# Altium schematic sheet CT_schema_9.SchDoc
size 391 x 238 mm
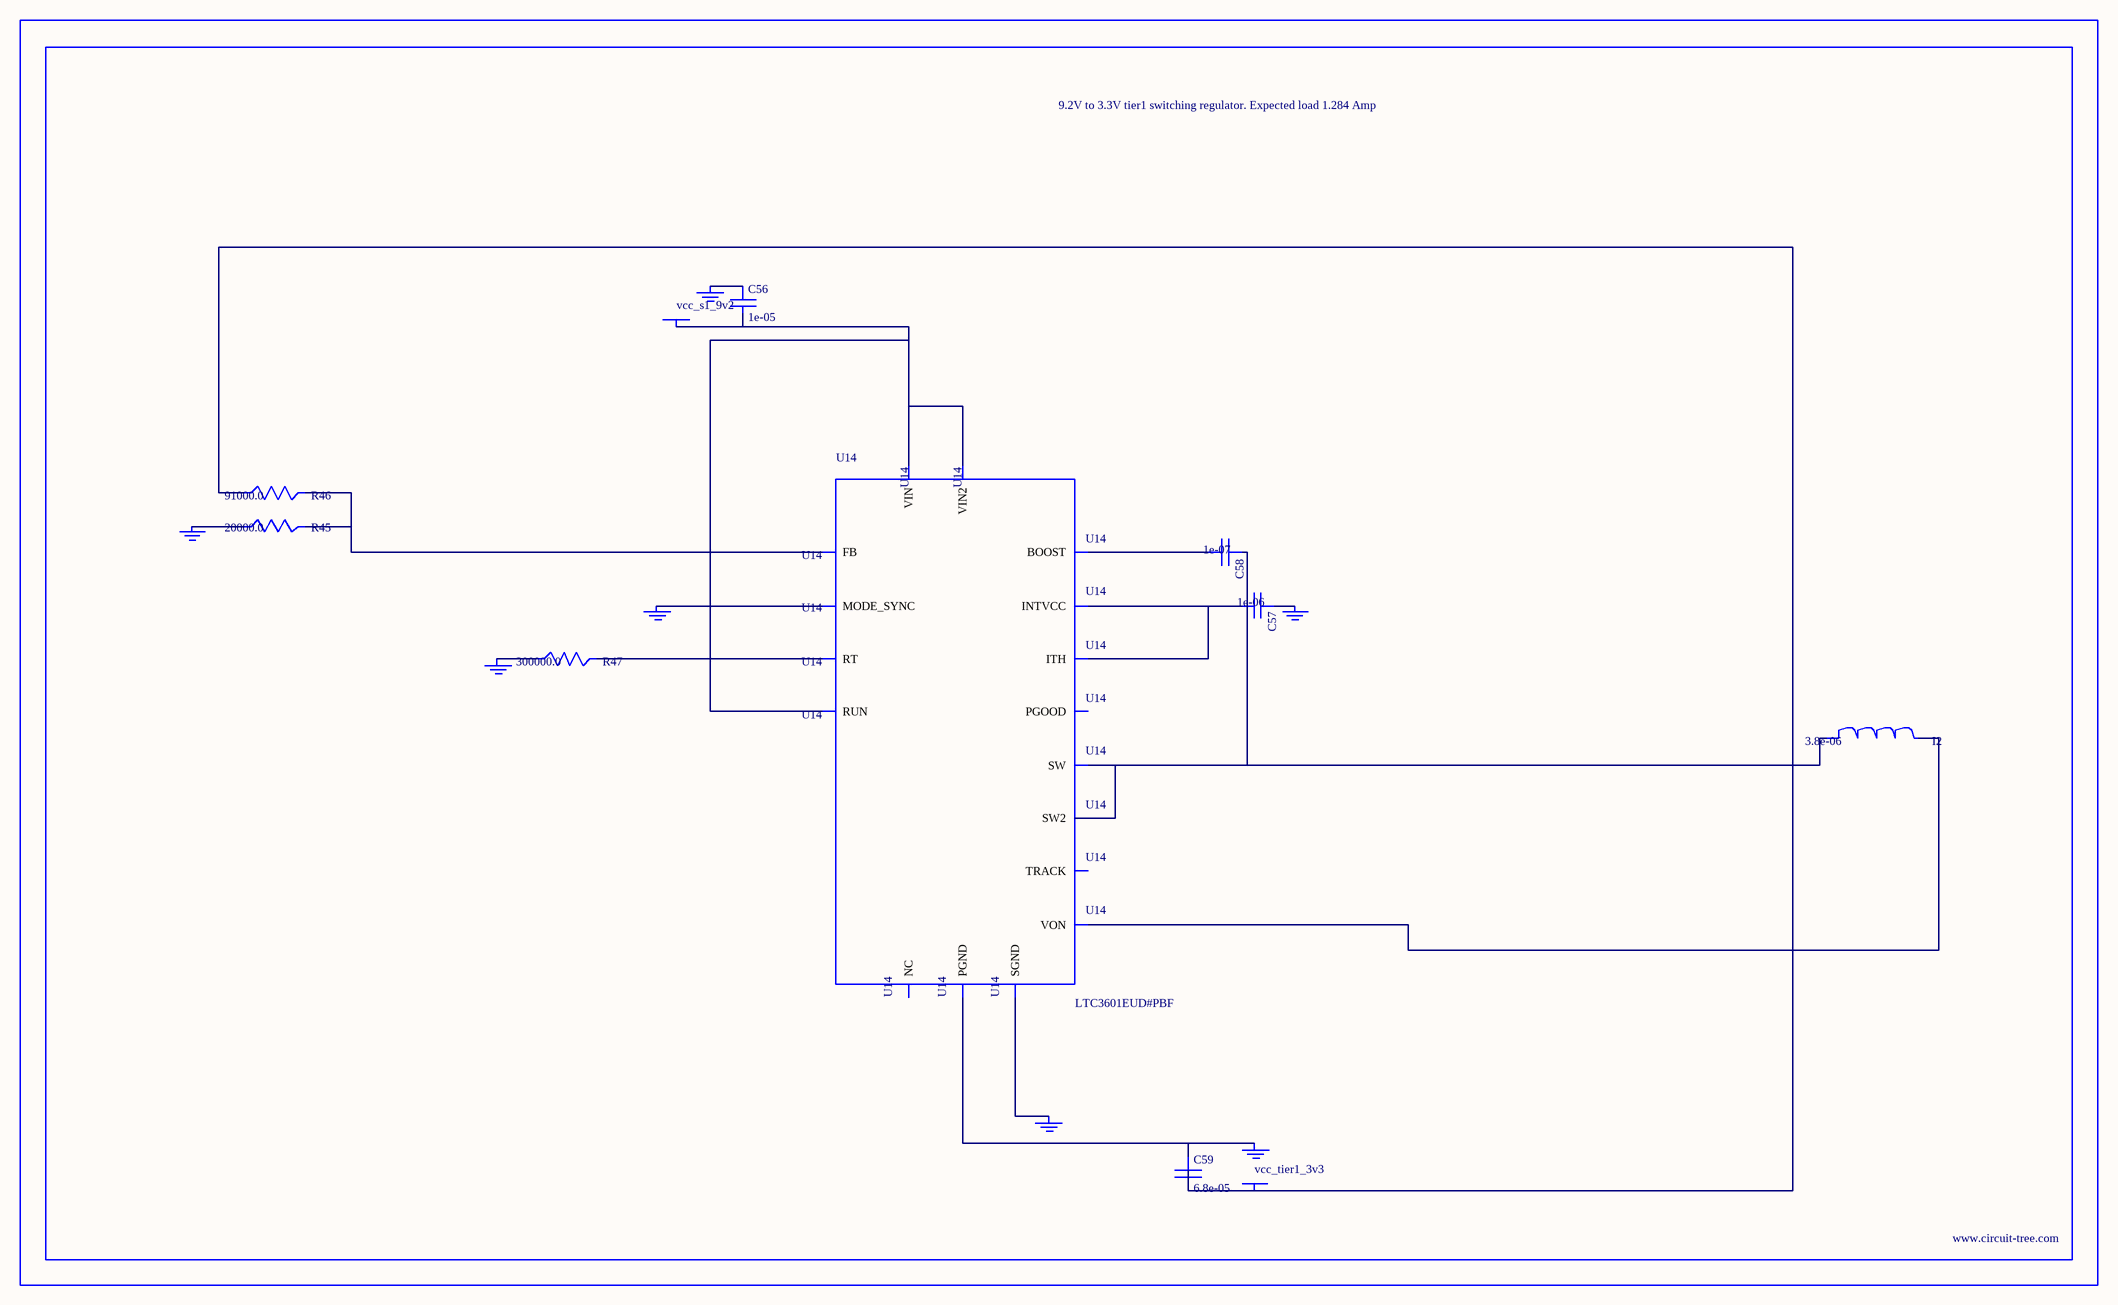
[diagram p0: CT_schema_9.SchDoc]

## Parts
BORDER8  (no value)
C56  1e-05  [C0805]
C57  1e-06  [C0603]
C58  1e-07  [C0402]
C59  6.8e-05  [2220]
GND_INSTANCE_8_0  (no value)
GND_INSTANCE_8_1  (no value)
GND_INSTANCE_8_2  (no value)
GND_INSTANCE_8_3  (no value)
GND_INSTANCE_8_4  (no value)
GND_INSTANCE_8_5  (no value)
GND_INSTANCE_8_6  (no value)
I2  3.8e-06  [DR1040]
POWER_INSTANCE_8_0  vcc_s1_9v2
POWER_INSTANCE_8_1  vcc_tier1_3v3
R45  20000.0  [R0603]
R46  91000.0  [R0603]
R47  300000.0  [R0603]
U14  LTC3601EUD#PBF  [QFN-16_EP]

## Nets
NetC56_1: C56.1 GND_INSTANCE_8_5.0(GND)
NetC56_2: C56.2 POWER_INSTANCE_8_0.0(PWR) U14.14(RUN) U14.15(VIN) U14.16(VIN2)
NetC57_1: C57.1 GND_INSTANCE_8_1.0(GND)
NetC57_2: C57.2 U14.7(INTVCC) U14.12(ITH)
NetC58_1: C58.1 I2.1 U14.3(SW) U14.4(SW2)
NetC58_2: C58.2 U14.6(BOOST)
NetC59_1: C59.1 GND_INSTANCE_8_6.0(GND) U14.17(PGND)
NetC59_2: C59.2 I2.2 POWER_INSTANCE_8_1.0(PWR) R46.1 U14.8(VON)
NetGND_INSTANCE_8_0_0: GND_INSTANCE_8_0.0(GND) U14.1(MODE_SYNC)
NetGND_INSTANCE_8_2_0: GND_INSTANCE_8_2.0(GND) U14.9(SGND)
NetGND_INSTANCE_8_3_0: GND_INSTANCE_8_3.0(GND) R47.1
NetGND_INSTANCE_8_4_0: GND_INSTANCE_8_4.0(GND) R45.1
NetR45_2: R45.2 R46.2 U14.11(FB)
NetR47_2: R47.2 U14.10(RT)

Not connected (* = marked no-connect by the designer): U14 2(PGOOD) 5(NC) 13(TRACK)

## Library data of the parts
BORDER8 = BORDER_PAGE8
C56 = C0805C106K8RACTU
C57 = C0603C105K3RACTU
C58 = C0402C104K3RACTU
C59 = C5750X5R1A686M
GND_INSTANCE_8_0-GND_INSTANCE_8_6 = GND
I2 = DR1040-3R8-R
POWER_INSTANCE_8_0 POWER_INSTANCE_8_1 = PWR
R45 = RC0603JR-0720KL
R46 = RC0603JR-0791KL
R47 = RC0603JR-07300KL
